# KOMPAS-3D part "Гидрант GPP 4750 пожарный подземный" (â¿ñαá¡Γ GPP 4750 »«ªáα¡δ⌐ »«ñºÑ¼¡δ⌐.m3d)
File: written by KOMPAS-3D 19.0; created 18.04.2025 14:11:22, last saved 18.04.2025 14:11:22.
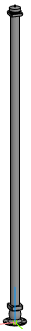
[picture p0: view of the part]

Document properties: Полное имя файла: E:\Dendor Работа Сачек\3D для проекитирвщиков\11.1 Тип GPP. Гидрант пожарный подземный\stp_Тип GPP. 750-6000 Гидрант пожарный подземный\Гидрант GPP 4750 пожарный подземный.m3d

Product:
- Part/product: Гидрант GPP 4750 пожарный подземный

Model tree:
1. Операция без истории:1  (labels: Гидрант GPP 4750 пожарный подземный)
